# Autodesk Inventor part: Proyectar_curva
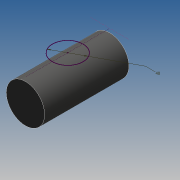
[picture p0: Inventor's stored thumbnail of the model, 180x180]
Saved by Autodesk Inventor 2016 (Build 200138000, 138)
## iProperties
Created: 2015-09
Part Number: Proyectar_curva
Material: Rubber
Document SubType Name: Modeling
Designer: julian.chica
Density: 0.93 g/cm^3
Appearance: Rubber - Black
Mass: 17.9683 g
Surface Area: 387.723 cm^2
Volume: 19.3208 cm^3
Author: julian.chica
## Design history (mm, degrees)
sketch "Sketch1"
  geometry: C1 r 25 at (0, 0); 1 further point
  constraints: 1 centre point, 1 coincident
  dimensions: "d0" = 50 diameter of C1
extrude "Extrusion1" new body sketch "Sketch1" distance "d1" = 110; taper "d2" = 0 deg
workplane "Work Plane1"
sketch "CIRCUNFERENCIA"
  geometry: L1 (25, 110)-(-25, 110) reference; L2 (0, 110)-(0, 0); C1 r 20 at (0, 55)
  constraints: 2 end point, 2 midpoint, 1 centre point, 1 vertical
  dimensions: "d4" = 40 diameter of C1
body "Solid1"
